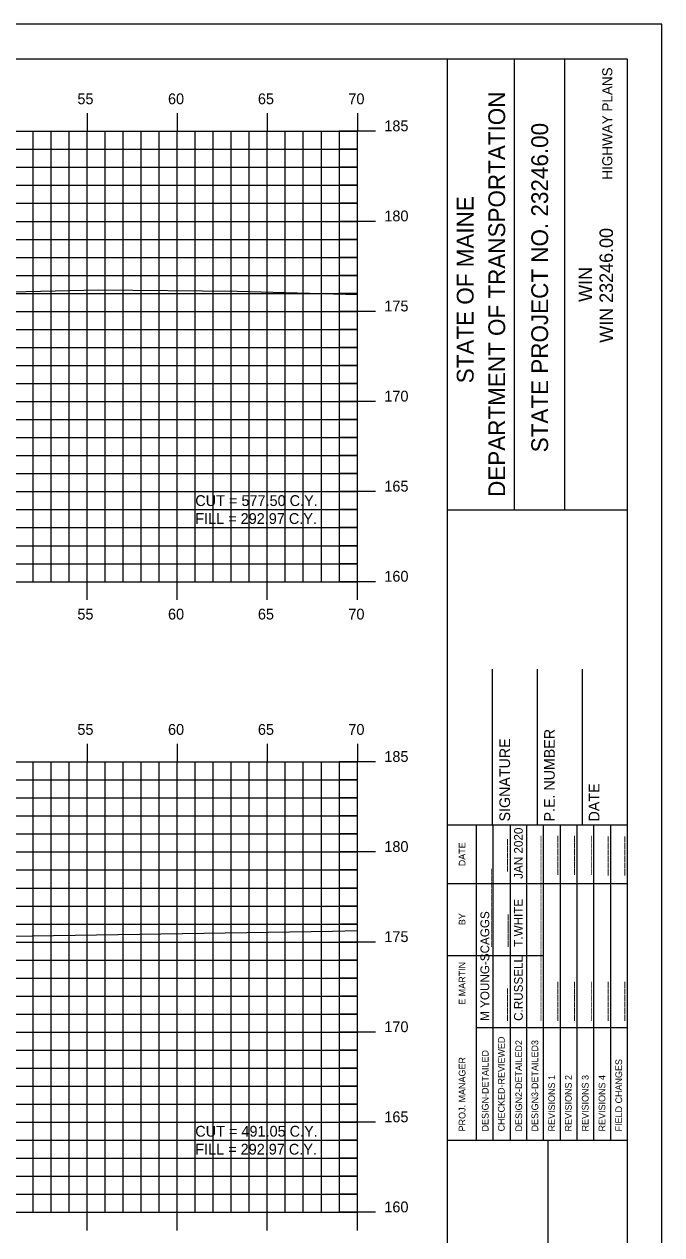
# Model space of a CAD drawing. Extents: x 1140537 to 1140707, y 608981 to 609091.
# Drawn here: x 1140671.7 to 1140707.2, y 609024.1 to 609091.3 of the extents above; entities that cross this region are included whole.
import ezdxf

# ---------------------------------------------------------------- set-up
doc = ezdxf.new("R2010")
doc.units = 0
for name, color, linetype in [('BORDER', 7, 'Continuous'), ('D_Text_Standard', 7, 'Continuous'), ('H_V ANNOTATION', 7, 'Continuous'), ('HIGHWAY_TITLE', 7, 'Continuous'), ('MAJOR', 7, 'Continuous'), ('MINOR', 7, 'Continuous'), ('PLOT BOUNDARY', 7, 'Continuous'), ('S_Roadway_Centerline', 7, 'Continuous')]:
    doc.layers.add(name, color=color, linetype=linetype)

msp = doc.modelspace()

# ---------------------------------------------------------------- linework, layer by layer
at = {"layer": 'BORDER'}
for p, q in [((1140695.245, 608984.335), (1140695.245, 609089.335)), ((1140698.973, 609064.332), (1140698.973, 609089.332)), ((1140701.768, 609064.332), (1140701.768, 609089.332)), ((1140695.246, 609064.329), (1140705.245, 609064.329)), ((1140697.745, 609046.838), (1140697.745, 609055.485)), ((1140700.245, 609046.838), (1140700.245, 609055.485)), ((1140702.745, 609046.838), (1140702.745, 609055.485)), ((1140695.245, 609046.838), (1140705.245, 609046.838)), ((1140695.245, 609029.338), (1140705.245, 609029.338)), ((1140700.836, 608994.338), (1140700.836, 609029.338))]:
    msp.add_line(p, q, dxfattribs=at)
msp.add_lwpolyline([(1140545.245, 608984.335), (1140705.245, 608984.335), (1140705.245, 609089.335), (1140545.245, 609089.335)], close=True, dxfattribs=at)
for points in [[(1140696.86, 609043.588), (1140696.86, 609046.838)], [(1140697.792, 609029.341), (1140697.792, 609046.838)], [(1140698.724, 609046.838), (1140698.724, 609029.341)], [(1140699.656, 609029.341), (1140699.656, 609046.838)], [(1140700.587, 609029.341), (1140700.587, 609046.838)], [(1140701.519, 609029.341), (1140701.519, 609046.838)], [(1140702.451, 609029.341), (1140702.451, 609046.838)], [(1140703.382, 609029.341), (1140703.382, 609046.838)], [(1140704.314, 609029.341), (1140704.314, 609046.838)], [(1140696.86, 609029.341), (1140696.86, 609046.132)], [(1140695.245, 609043.588), (1140705.245, 609043.588)], [(1140695.245, 609039.588), (1140696.86, 609039.588)], [(1140696.86, 609039.588), (1140700.586, 609039.588)], [(1140696.86, 609035.588), (1140705.245, 609035.588)]]:
    msp.add_lwpolyline(points, dxfattribs=at)
at = {"layer": 'MAJOR'}
for p, q in [((1140675.245, 609086.337), (1140675.245, 609085.335)), ((1140680.245, 609086.337), (1140680.245, 609085.335)), ((1140685.245, 609086.337), (1140685.245, 609085.335)), ((1140690.245, 609086.337), (1140690.245, 609085.335)), ((1140550.245, 609085.335), (1140690.245, 609085.335)), ((1140550.245, 609085.335), (1140690.245, 609085.335)), ((1140675.245, 609060.335), (1140675.245, 609085.335)), ((1140680.245, 609060.335), (1140680.245, 609085.335)), ((1140685.245, 609060.335), (1140685.245, 609085.335)), ((1140691.247, 609085.335), (1140689.243, 609085.335)), ((1140690.245, 609060.335), (1140690.245, 609085.335)), ((1140690.245, 609060.335), (1140690.245, 609085.335)), ((1140550.245, 609080.335), (1140690.245, 609080.335)), ((1140691.247, 609080.335), (1140689.243, 609080.335)), ((1140550.245, 609075.335), (1140690.245, 609075.335)), ((1140691.247, 609075.335), (1140689.243, 609075.335)), ((1140550.245, 609070.335), (1140690.245, 609070.335)), ((1140691.247, 609070.335), (1140689.243, 609070.335)), ((1140550.245, 609065.335), (1140690.245, 609065.335)), ((1140691.247, 609065.335), (1140689.243, 609065.335)), ((1140550.245, 609060.335), (1140690.245, 609060.335)), ((1140550.245, 609060.335), (1140690.245, 609060.335)), ((1140675.245, 609059.333), (1140675.245, 609060.335)), ((1140680.245, 609059.333), (1140680.245, 609060.335)), ((1140685.245, 609059.333), (1140685.245, 609060.335)), ((1140691.247, 609060.335), (1140689.243, 609060.335)), ((1140690.245, 609059.333), (1140690.245, 609060.335)), ((1140675.245, 609051.337), (1140675.245, 609050.335)), ((1140680.245, 609051.337), (1140680.245, 609050.335)), ((1140685.245, 609051.337), (1140685.245, 609050.335)), ((1140690.245, 609051.337), (1140690.245, 609050.335)), ((1140550.245, 609050.335), (1140690.245, 609050.335)), ((1140550.245, 609050.335), (1140690.245, 609050.335)), ((1140675.245, 609025.335), (1140675.245, 609050.335)), ((1140680.245, 609025.335), (1140680.245, 609050.335)), ((1140685.245, 609025.335), (1140685.245, 609050.335)), ((1140691.247, 609050.335), (1140689.243, 609050.335)), ((1140690.245, 609025.335), (1140690.245, 609050.335)), ((1140690.245, 609025.335), (1140690.245, 609050.335)), ((1140550.245, 609045.335), (1140690.245, 609045.335)), ((1140691.247, 609045.335), (1140689.243, 609045.335)), ((1140550.245, 609040.335), (1140690.245, 609040.335)), ((1140691.247, 609040.335), (1140689.243, 609040.335)), ((1140550.245, 609035.335), (1140690.245, 609035.335)), ((1140691.247, 609035.335), (1140689.243, 609035.335)), ((1140550.245, 609030.335), (1140690.245, 609030.335)), ((1140691.247, 609030.335), (1140689.243, 609030.335)), ((1140550.245, 609025.335), (1140690.245, 609025.335)), ((1140550.245, 609025.335), (1140690.245, 609025.335)), ((1140675.245, 609024.333), (1140675.245, 609025.335)), ((1140680.245, 609024.333), (1140680.245, 609025.335)), ((1140685.245, 609024.333), (1140685.245, 609025.335)), ((1140691.247, 609025.335), (1140689.243, 609025.335)), ((1140690.245, 609024.333), (1140690.245, 609025.335))]:
    msp.add_line(p, q, dxfattribs=at)
at = {"layer": 'MINOR'}
for p, q in [((1140672.245, 609060.335), (1140672.245, 609085.335)), ((1140673.245, 609060.335), (1140673.245, 609085.335)), ((1140674.245, 609060.335), (1140674.245, 609085.335)), ((1140676.245, 609060.335), (1140676.245, 609085.335)), ((1140677.245, 609060.335), (1140677.245, 609085.335)), ((1140678.245, 609060.335), (1140678.245, 609085.335)), ((1140679.245, 609060.335), (1140679.245, 609085.335)), ((1140681.245, 609060.335), (1140681.245, 609085.335)), ((1140682.245, 609060.335), (1140682.245, 609085.335)), ((1140683.245, 609060.335), (1140683.245, 609085.335)), ((1140684.245, 609060.335), (1140684.245, 609085.335)), ((1140686.245, 609060.335), (1140686.245, 609085.335)), ((1140687.245, 609060.335), (1140687.245, 609085.335)), ((1140688.245, 609060.335), (1140688.245, 609085.335)), ((1140689.245, 609060.335), (1140689.245, 609085.335)), ((1140550.245, 609084.335), (1140690.245, 609084.335)), ((1140690.245, 609084.335), (1140689.243, 609084.335)), ((1140550.245, 609083.335), (1140690.245, 609083.335)), ((1140690.245, 609083.335), (1140689.243, 609083.335)), ((1140550.245, 609082.335), (1140690.245, 609082.335)), ((1140690.245, 609082.335), (1140689.243, 609082.335)), ((1140550.245, 609081.335), (1140690.245, 609081.335)), ((1140690.245, 609081.335), (1140689.243, 609081.335)), ((1140550.245, 609079.335), (1140690.245, 609079.335)), ((1140690.245, 609079.335), (1140689.243, 609079.335)), ((1140550.245, 609078.335), (1140690.245, 609078.335)), ((1140690.245, 609078.335), (1140689.243, 609078.335)), ((1140550.245, 609077.335), (1140690.245, 609077.335)), ((1140690.245, 609077.335), (1140689.243, 609077.335)), ((1140550.245, 609076.335), (1140690.245, 609076.335)), ((1140690.245, 609076.335), (1140689.243, 609076.335)), ((1140550.245, 609074.335), (1140690.245, 609074.335)), ((1140690.245, 609074.335), (1140689.243, 609074.335)), ((1140550.245, 609073.335), (1140690.245, 609073.335)), ((1140690.245, 609073.335), (1140689.243, 609073.335)), ((1140550.245, 609072.335), (1140690.245, 609072.335)), ((1140690.245, 609072.335), (1140689.243, 609072.335)), ((1140550.245, 609071.335), (1140690.245, 609071.335)), ((1140690.245, 609071.335), (1140689.243, 609071.335)), ((1140550.245, 609069.335), (1140690.245, 609069.335)), ((1140690.245, 609069.335), (1140689.243, 609069.335)), ((1140550.245, 609068.335), (1140690.245, 609068.335)), ((1140690.245, 609068.335), (1140689.243, 609068.335)), ((1140550.245, 609067.335), (1140690.245, 609067.335)), ((1140690.245, 609067.335), (1140689.243, 609067.335)), ((1140550.245, 609066.335), (1140690.245, 609066.335)), ((1140690.245, 609066.335), (1140689.243, 609066.335)), ((1140550.245, 609064.335), (1140690.245, 609064.335)), ((1140690.245, 609064.335), (1140689.243, 609064.335)), ((1140550.245, 609063.335), (1140690.245, 609063.335)), ((1140690.245, 609063.335), (1140689.243, 609063.335)), ((1140550.245, 609062.335), (1140690.245, 609062.335)), ((1140690.245, 609062.335), (1140689.243, 609062.335)), ((1140550.245, 609061.335), (1140690.245, 609061.335)), ((1140690.245, 609061.335), (1140689.243, 609061.335)), ((1140672.245, 609025.335), (1140672.245, 609050.335)), ((1140673.245, 609025.335), (1140673.245, 609050.335)), ((1140674.245, 609025.335), (1140674.245, 609050.335)), ((1140676.245, 609025.335), (1140676.245, 609050.335)), ((1140677.245, 609025.335), (1140677.245, 609050.335)), ((1140678.245, 609025.335), (1140678.245, 609050.335)), ((1140679.245, 609025.335), (1140679.245, 609050.335)), ((1140681.245, 609025.335), (1140681.245, 609050.335)), ((1140682.245, 609025.335), (1140682.245, 609050.335)), ((1140683.245, 609025.335), (1140683.245, 609050.335)), ((1140684.245, 609025.335), (1140684.245, 609050.335)), ((1140686.245, 609025.335), (1140686.245, 609050.335)), ((1140687.245, 609025.335), (1140687.245, 609050.335)), ((1140688.245, 609025.335), (1140688.245, 609050.335)), ((1140689.245, 609025.335), (1140689.245, 609050.335)), ((1140550.245, 609049.335), (1140690.245, 609049.335)), ((1140690.245, 609049.335), (1140689.243, 609049.335)), ((1140550.245, 609048.335), (1140690.245, 609048.335)), ((1140690.245, 609048.335), (1140689.243, 609048.335)), ((1140550.245, 609047.335), (1140690.245, 609047.335)), ((1140690.245, 609047.335), (1140689.243, 609047.335)), ((1140550.245, 609046.335), (1140690.245, 609046.335)), ((1140690.245, 609046.335), (1140689.243, 609046.335)), ((1140550.245, 609044.335), (1140690.245, 609044.335)), ((1140690.245, 609044.335), (1140689.243, 609044.335)), ((1140550.245, 609043.335), (1140690.245, 609043.335)), ((1140690.245, 609043.335), (1140689.243, 609043.335)), ((1140550.245, 609042.335), (1140690.245, 609042.335)), ((1140690.245, 609042.335), (1140689.243, 609042.335)), ((1140550.245, 609041.335), (1140690.245, 609041.335)), ((1140690.245, 609041.335), (1140689.243, 609041.335)), ((1140550.245, 609039.335), (1140690.245, 609039.335)), ((1140690.245, 609039.335), (1140689.243, 609039.335)), ((1140550.245, 609038.335), (1140690.245, 609038.335)), ((1140690.245, 609038.335), (1140689.243, 609038.335)), ((1140550.245, 609037.335), (1140690.245, 609037.335)), ((1140690.245, 609037.335), (1140689.243, 609037.335)), ((1140550.245, 609036.335), (1140690.245, 609036.335)), ((1140690.245, 609036.335), (1140689.243, 609036.335)), ((1140550.245, 609034.335), (1140690.245, 609034.335)), ((1140690.245, 609034.335), (1140689.243, 609034.335)), ((1140550.245, 609033.335), (1140690.245, 609033.335)), ((1140690.245, 609033.335), (1140689.243, 609033.335)), ((1140550.245, 609032.335), (1140690.245, 609032.335)), ((1140690.245, 609032.335), (1140689.243, 609032.335)), ((1140550.245, 609031.335), (1140690.245, 609031.335)), ((1140690.245, 609031.335), (1140689.243, 609031.335)), ((1140550.245, 609029.335), (1140690.245, 609029.335)), ((1140690.245, 609029.335), (1140689.243, 609029.335)), ((1140550.245, 609028.335), (1140690.245, 609028.335)), ((1140690.245, 609028.335), (1140689.243, 609028.335)), ((1140550.245, 609027.335), (1140690.245, 609027.335)), ((1140690.245, 609027.335), (1140689.243, 609027.335)), ((1140550.245, 609026.335), (1140690.245, 609026.335)), ((1140690.245, 609026.335), (1140689.243, 609026.335))]:
    msp.add_line(p, q, dxfattribs=at)
at = {"layer": 'PLOT BOUNDARY'}
msp.add_lwpolyline([(1140537.151, 608981.276), (1140707.151, 608981.276), (1140707.151, 609091.276), (1140537.151, 609091.276)], close=True, dxfattribs=at)
at = {"layer": 'S_Roadway_Centerline'}
for points in [[(1140635.963, 609072.743), (1140636.719, 609072.645), (1140638.275, 609072.761), (1140644.695, 609075.761), (1140659.062, 609076.141), (1140675.851, 609076.536), (1140683.575, 609076.463), (1140690.245, 609076.267)], [(1140635.028, 609040.273), (1140638.111, 609039.824), (1140638.885, 609039.859), (1140642.483, 609040.354), (1140655.858, 609040.472), (1140668.593, 609040.618), (1140688.858, 609040.948), (1140690.245, 609040.968)]]:
    msp.add_lwpolyline(points, dxfattribs=at)

# ---------------------------------------------------------------- texts
at = {"layer": 'BORDER'}
for s, height, p in [('DEPARTMENT OF TRANSPORTATION', 0.93176, (1140698.452, 609065.041)), ('STATE PROJECT NO. 23246.00', 0.93176, (1140700.837, 609067.517)), ('STATE OF MAINE', 0.93176, (1140696.7, 609071.347)), ('WIN 23246.00', 0.74527, (1140704.44, 609073.596)), ('WIN', 0.7453, (1140703.281, 609075.865)), ('P.E. NUMBER', 0.59055, (1140701.205, 609047.03)), ('SIGNATURE', 0.5906, (1140698.725, 609047.03)), ('DATE', 0.5906, (1140703.686, 609047.03)), ('JAN 2020', 0.4845, (1140699.431, 609043.843)), ('DATE', 0.3714, (1140696.249, 609044.544)), ('_____', 0.4845, (1140698.462, 609044.243)), ('______', 0.4845, (1140700.325, 609044.063)), ('______', 0.4845, (1140701.257, 609044.065)), ('______', 0.4845, (1140702.189, 609044.067)), ('______', 0.4845, (1140703.12, 609044.067)), ('______', 0.4845, (1140704.052, 609044.036)), ('______', 0.4845, (1140704.984, 609044.036)), ('____________', 0.48455, (1140697.568, 609040.073)), ('____________', 0.48455, (1140700.325, 609040.073)), ('T.WHITE', 0.4845, (1140699.431, 609040.073)), ('BY', 0.3714, (1140696.249, 609041.273)), ('M YOUNG-SCAGGS', 0.48455, (1140697.568, 609035.961)), ('_____', 0.4845, (1140698.499, 609040.073)), ('____________', 0.48455, (1140700.325, 609035.961)), ('E MARTIN', 0.3727, (1140696.249, 609036.855)), ('C.RUSSELL', 0.4845, (1140699.431, 609035.961)), ('_____', 0.4845, (1140698.462, 609035.961)), ('______', 0.4845, (1140701.257, 609035.961)), ('______', 0.4845, (1140702.189, 609035.961)), ('______', 0.4845, (1140703.12, 609035.961)), ('______', 0.4845, (1140704.052, 609035.961)), ('______', 0.4845, (1140704.984, 609035.961)), ('CHECKED-REVIEWED', 0.37275, (1140698.426, 609029.826)), ('DESIGN2-DETAILED2', 0.37275, (1140699.395, 609029.826)), ('DESIGN3-DETAILED3', 0.37275, (1140700.289, 609029.826)), ('DESIGN-DETAILED', 0.37275, (1140697.531, 609029.826)), ('PROJ. MANAGER', 0.37275, (1140696.249, 609029.826)), ('FIELD CHANGES', 0.37275, (1140704.947, 609029.826)), ('REVISIONS 1', 0.37275, (1140701.221, 609029.826)), ('REVISIONS 2', 0.37275, (1140702.152, 609029.826)), ('REVISIONS 3', 0.37275, (1140703.084, 609029.826)), ('REVISIONS 4', 0.37275, (1140704.016, 609029.826))]:
    msp.add_text(s, height=height, rotation=90, dxfattribs=at).set_placement(p)
at = {"layer": 'D_Text_Standard'}
for s, p in [('CUT = 577.50 C.Y.', (1140681.245, 609064.535)), ('FILL = 292.97 C.Y.', (1140681.245, 609063.539)), ('CUT = 491.05 C.Y.', (1140681.245, 609029.535)), ('FILL = 292.97 C.Y.', (1140681.245, 609028.539))]:
    msp.add_text(s, height=0.6, dxfattribs=at).set_placement(p)
at = {"layer": 'H_V ANNOTATION'}
for s, p in [('55', (1140674.701, 609086.835)), ('60', (1140679.731, 609086.835)), ('65', (1140684.723, 609086.835)), ('70', (1140689.747, 609086.835)), ('185', (1140691.745, 609085.335)), ('180', (1140691.745, 609080.335)), ('175', (1140691.745, 609075.335)), ('170', (1140691.745, 609070.335)), ('165', (1140691.745, 609065.335)), ('160', (1140691.745, 609060.335)), ('55', (1140674.701, 609058.235)), ('60', (1140679.731, 609058.235)), ('65', (1140684.723, 609058.235)), ('70', (1140689.747, 609058.235)), ('55', (1140674.701, 609051.835)), ('60', (1140679.731, 609051.835)), ('65', (1140684.723, 609051.835)), ('70', (1140689.747, 609051.835)), ('185', (1140691.745, 609050.335)), ('180', (1140691.745, 609045.335)), ('175', (1140691.745, 609040.335)), ('170', (1140691.745, 609035.335)), ('165', (1140691.745, 609030.335)), ('160', (1140691.745, 609025.335))]:
    msp.add_text(s, height=0.6, dxfattribs=at).set_placement(p)
at = {"layer": 'HIGHWAY_TITLE'}
msp.add_text('HIGHWAY PLANS', height=0.55901, rotation=90, dxfattribs=at).set_placement((1140704.403, 609082.65))

doc.saveas('drawing.dxf')
